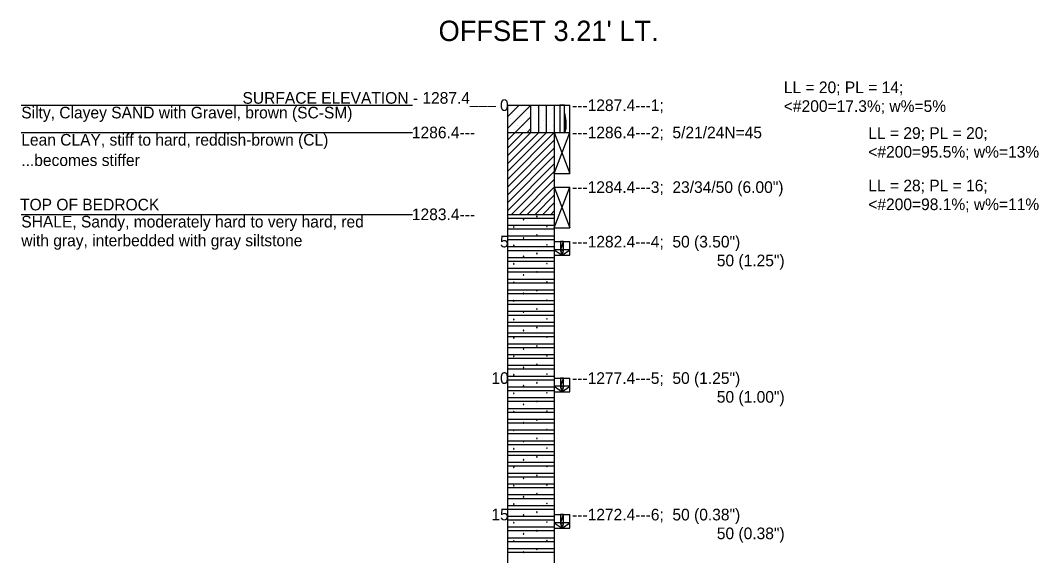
# Model space of a CAD drawing. Extents: x -6 to 173, y 24 to 64.
# Drawn here: x 54.9 to 65.75, y 44.93 to 50.63 of the extents above; entities that cross this region are included whole.
import ezdxf

# ---------------------------------------------------------------- set-up
doc = ezdxf.new("R2010")
doc.units = 0

# ---------------------------------------------------------------- blocks, each defined once
blk = doc.blocks.new('POINT_DISPLAY')
blk.add_line((0, 0), (0, 0))

msp = doc.modelspace()

# ---------------------------------------------------------------- linework, layer by layer
for points in [[(54.91, 49.727), (59.077, 49.727)], [(60.089, 49.602), (60.214, 49.727)], [(60.089, 49.477), (60.339, 49.727)], [(60.089, 49.727), (60.089, 39.553)], [(60.089, 49.727), (60.589, 49.727)], [(60.339, 49.436), (60.339, 49.727)], [(60.423, 49.436), (60.423, 49.727)], [(60.506, 49.436), (60.506, 49.727)], [(60.589, 49.727), (60.756, 49.727)], [(60.589, 49.727), (60.589, 39.553)], [(60.756, 49.436), (60.756, 49.727)], [(60.174, 49.436), (60.339, 49.602)], [(60.299, 49.436), (60.339, 49.477)], [(54.91, 49.436), (59.077, 49.436)], [(60.089, 49.436), (60.589, 49.436)], [(60.089, 49.353), (60.173, 49.436)], [(60.089, 49.27), (60.256, 49.436)], [(60.089, 49.186), (60.339, 49.436)], [(60.089, 49.103), (60.423, 49.436)], [(60.089, 49.02), (60.506, 49.436)], [(60.089, 48.936), (60.589, 49.436)], [(60.589, 49.436), (60.756, 49.436)], [(60.589, 49.436), (60.756, 49)], [(60.589, 49), (60.756, 49.436)], [(60.589, 49.436), (60.756, 49.436)], [(60.756, 49), (60.756, 49.436)], [(60.089, 48.853), (60.589, 49.353)], [(60.089, 48.77), (60.589, 49.27)], [(60.089, 48.686), (60.589, 49.186)], [(60.089, 48.603), (60.589, 49.103)], [(60.134, 48.564), (60.589, 49.02)], [(60.217, 48.564), (60.589, 48.936)], [(60.589, 49), (60.756, 49)], [(60.301, 48.564), (60.589, 48.853)], [(60.589, 48.855), (60.756, 48.419)], [(60.589, 48.419), (60.756, 48.855)], [(60.589, 48.855), (60.756, 48.855)], [(60.756, 48.419), (60.756, 48.855)], [(60.384, 48.564), (60.589, 48.77)], [(60.467, 48.564), (60.589, 48.686)], [(54.91, 48.564), (59.077, 48.564)], [(60.089, 48.564), (60.589, 48.564)], [(60.089, 48.564), (60.589, 48.564)], [(60.089, 48.525), (60.589, 48.525)], [(60.264, 48.508), (60.263, 48.511), (60.26, 48.511), (60.258, 48.509), (60.26, 48.506), (60.263, 48.506), (60.264, 48.508)], [(60.407, 48.54), (60.405, 48.543), (60.402, 48.543), (60.4, 48.54), (60.402, 48.538), (60.405, 48.538), (60.407, 48.54)], [(60.551, 48.564), (60.589, 48.603)], [(60.089, 48.449), (60.589, 48.449)], [(60.089, 48.41), (60.589, 48.41)], [(60.16, 48.43), (60.158, 48.432), (60.155, 48.432), (60.153, 48.43), (60.155, 48.427), (60.158, 48.427), (60.16, 48.43)], [(60.513, 48.436), (60.511, 48.439), (60.508, 48.439), (60.506, 48.436), (60.508, 48.433), (60.511, 48.433), (60.513, 48.436)], [(60.589, 48.419), (60.756, 48.419)], [(60.089, 48.335), (60.589, 48.335)], [(60.089, 48.295), (60.589, 48.295)], [(60.264, 48.312), (60.263, 48.314), (60.26, 48.314), (60.258, 48.312), (60.26, 48.309), (60.263, 48.309), (60.264, 48.312)], [(60.407, 48.343), (60.405, 48.346), (60.402, 48.346), (60.4, 48.343), (60.402, 48.341), (60.405, 48.341), (60.407, 48.343)], [(60.089, 48.22), (60.589, 48.22)], [(60.089, 48.18), (60.589, 48.18)], [(60.16, 48.233), (60.158, 48.235), (60.155, 48.235), (60.153, 48.233), (60.155, 48.23), (60.158, 48.23), (60.16, 48.233)], [(60.513, 48.239), (60.511, 48.242), (60.508, 48.242), (60.506, 48.239), (60.508, 48.236), (60.511, 48.236), (60.513, 48.239)], [(60.589, 48.274), (60.756, 48.274)], [(60.756, 48.128), (60.756, 48.274)], [(60.089, 48.105), (60.589, 48.105)], [(60.089, 48.066), (60.589, 48.066)], [(60.264, 48.115), (60.263, 48.118), (60.26, 48.118), (60.258, 48.115), (60.26, 48.112), (60.263, 48.112), (60.264, 48.115)], [(60.407, 48.147), (60.405, 48.149), (60.402, 48.149), (60.4, 48.147), (60.402, 48.144), (60.405, 48.144), (60.407, 48.147)], [(60.589, 48.128), (60.756, 48.128)], [(60.089, 47.99), (60.589, 47.99)], [(60.16, 48.036), (60.158, 48.039), (60.155, 48.039), (60.153, 48.036), (60.155, 48.033), (60.158, 48.033), (60.16, 48.036)], [(60.513, 48.042), (60.511, 48.045), (60.508, 48.045), (60.506, 48.042), (60.508, 48.039), (60.511, 48.039), (60.513, 48.042)], [(60.089, 47.951), (60.589, 47.951)], [(60.089, 47.875), (60.589, 47.875)], [(60.264, 47.918), (60.263, 47.921), (60.26, 47.921), (60.258, 47.918), (60.26, 47.915), (60.263, 47.915), (60.264, 47.918)], [(60.407, 47.95), (60.405, 47.953), (60.402, 47.953), (60.4, 47.95), (60.402, 47.947), (60.405, 47.947), (60.407, 47.95)], [(60.513, 47.845), (60.511, 47.848), (60.508, 47.848), (60.506, 47.845), (60.508, 47.843), (60.511, 47.843), (60.513, 47.845)], [(60.089, 47.836), (60.589, 47.836)], [(60.089, 47.76), (60.589, 47.76)], [(60.16, 47.839), (60.158, 47.842), (60.155, 47.842), (60.153, 47.839), (60.155, 47.836), (60.158, 47.836), (60.16, 47.839)], [(60.407, 47.753), (60.405, 47.756), (60.402, 47.756), (60.4, 47.753), (60.402, 47.75), (60.405, 47.75), (60.407, 47.753)], [(60.089, 47.721), (60.589, 47.721)], [(60.089, 47.646), (60.589, 47.646)], [(60.16, 47.642), (60.158, 47.645), (60.155, 47.645), (60.153, 47.642), (60.155, 47.639), (60.158, 47.639), (60.16, 47.642)], [(60.264, 47.721), (60.263, 47.724), (60.26, 47.724), (60.258, 47.721), (60.26, 47.718), (60.263, 47.718), (60.264, 47.721)], [(60.513, 47.649), (60.511, 47.651), (60.508, 47.651), (60.506, 47.649), (60.508, 47.646), (60.511, 47.646), (60.513, 47.649)], [(60.089, 47.606), (60.589, 47.606)], [(60.089, 47.531), (60.589, 47.531)], [(60.264, 47.524), (60.263, 47.527), (60.26, 47.527), (60.258, 47.524), (60.26, 47.521), (60.263, 47.521), (60.264, 47.524)], [(60.407, 47.556), (60.405, 47.559), (60.402, 47.559), (60.4, 47.556), (60.402, 47.553), (60.405, 47.553), (60.407, 47.556)], [(60.089, 47.491), (60.589, 47.491)], [(60.089, 47.416), (60.589, 47.416)], [(60.16, 47.445), (60.158, 47.448), (60.155, 47.448), (60.153, 47.445), (60.155, 47.442), (60.158, 47.442), (60.16, 47.445)], [(60.513, 47.452), (60.511, 47.455), (60.508, 47.455), (60.506, 47.452), (60.508, 47.449), (60.511, 47.449), (60.513, 47.452)], [(60.089, 47.377), (60.589, 47.377)], [(60.264, 47.327), (60.263, 47.33), (60.26, 47.33), (60.258, 47.327), (60.26, 47.325), (60.263, 47.325), (60.264, 47.327)], [(60.407, 47.359), (60.405, 47.362), (60.402, 47.362), (60.4, 47.359), (60.402, 47.356), (60.405, 47.356), (60.407, 47.359)], [(60.089, 47.301), (60.589, 47.301)], [(60.089, 47.262), (60.589, 47.262)], [(60.16, 47.248), (60.158, 47.251), (60.155, 47.251), (60.153, 47.248), (60.155, 47.246), (60.158, 47.246), (60.16, 47.248)], [(60.513, 47.255), (60.511, 47.258), (60.508, 47.258), (60.506, 47.255), (60.508, 47.252), (60.511, 47.252), (60.513, 47.255)], [(60.089, 47.186), (60.589, 47.186)], [(60.089, 47.147), (60.589, 47.147)], [(60.264, 47.13), (60.263, 47.133), (60.26, 47.133), (60.258, 47.131), (60.26, 47.128), (60.263, 47.128), (60.264, 47.13)], [(60.407, 47.162), (60.405, 47.165), (60.402, 47.165), (60.4, 47.162), (60.402, 47.16), (60.405, 47.16), (60.407, 47.162)], [(60.089, 47.072), (60.589, 47.072)], [(60.089, 47.032), (60.589, 47.032)], [(60.16, 47.052), (60.158, 47.054), (60.155, 47.054), (60.153, 47.052), (60.155, 47.049), (60.158, 47.049), (60.16, 47.052)], [(60.513, 47.058), (60.511, 47.061), (60.508, 47.061), (60.506, 47.058), (60.508, 47.055), (60.511, 47.055), (60.513, 47.058)], [(60.089, 46.957), (60.589, 46.957)], [(60.089, 46.917), (60.589, 46.917)], [(60.264, 46.934), (60.263, 46.937), (60.26, 46.937), (60.258, 46.934), (60.26, 46.931), (60.263, 46.931), (60.264, 46.934)], [(60.407, 46.966), (60.405, 46.968), (60.402, 46.968), (60.4, 46.966), (60.402, 46.963), (60.405, 46.963), (60.407, 46.966)], [(60.089, 46.842), (60.589, 46.842)], [(60.089, 46.802), (60.589, 46.802)], [(60.16, 46.855), (60.158, 46.858), (60.155, 46.858), (60.153, 46.855), (60.155, 46.852), (60.158, 46.852), (60.16, 46.855)], [(60.407, 46.769), (60.405, 46.772), (60.402, 46.772), (60.4, 46.769), (60.402, 46.766), (60.405, 46.766), (60.407, 46.769)], [(60.513, 46.861), (60.511, 46.864), (60.508, 46.864), (60.506, 46.861), (60.508, 46.858), (60.511, 46.858), (60.513, 46.861)], [(60.589, 46.82), (60.756, 46.82)], [(60.756, 46.675), (60.756, 46.82)], [(60.089, 46.727), (60.589, 46.727)], [(60.089, 46.688), (60.589, 46.688)], [(60.16, 46.658), (60.158, 46.661), (60.155, 46.661), (60.153, 46.658), (60.155, 46.655), (60.158, 46.655), (60.16, 46.658)], [(60.264, 46.737), (60.263, 46.74), (60.26, 46.74), (60.258, 46.737), (60.26, 46.734), (60.263, 46.734), (60.264, 46.737)], [(60.513, 46.664), (60.511, 46.667), (60.508, 46.667), (60.506, 46.664), (60.508, 46.662), (60.511, 46.662), (60.513, 46.664)], [(60.589, 46.675), (60.756, 46.675)], [(60.089, 46.612), (60.589, 46.612)], [(60.089, 46.573), (60.589, 46.573)], [(60.407, 46.572), (60.405, 46.575), (60.402, 46.575), (60.4, 46.572), (60.402, 46.569), (60.405, 46.569), (60.407, 46.572)], [(60.089, 46.497), (60.589, 46.497)], [(60.089, 46.458), (60.589, 46.458)], [(60.16, 46.461), (60.158, 46.464), (60.155, 46.464), (60.153, 46.461), (60.155, 46.458), (60.158, 46.458), (60.16, 46.461)], [(60.264, 46.54), (60.263, 46.543), (60.26, 46.543), (60.258, 46.54), (60.26, 46.537), (60.263, 46.537), (60.264, 46.54)], [(60.513, 46.468), (60.511, 46.47), (60.508, 46.47), (60.506, 46.468), (60.508, 46.465), (60.511, 46.465), (60.513, 46.468)], [(60.089, 46.383), (60.589, 46.383)], [(60.089, 46.343), (60.589, 46.343)], [(60.264, 46.343), (60.263, 46.346), (60.26, 46.346), (60.258, 46.343), (60.26, 46.34), (60.263, 46.34), (60.264, 46.343)], [(60.407, 46.375), (60.405, 46.378), (60.402, 46.378), (60.4, 46.375), (60.402, 46.372), (60.405, 46.372), (60.407, 46.375)], [(60.089, 46.268), (60.589, 46.268)], [(60.089, 46.228), (60.589, 46.228)], [(60.16, 46.264), (60.158, 46.267), (60.155, 46.267), (60.153, 46.264), (60.155, 46.261), (60.158, 46.261), (60.16, 46.264)], [(60.513, 46.271), (60.511, 46.274), (60.508, 46.274), (60.506, 46.271), (60.508, 46.268), (60.511, 46.268), (60.513, 46.271)], [(60.089, 46.153), (60.589, 46.153)], [(60.089, 46.114), (60.589, 46.114)], [(60.264, 46.146), (60.263, 46.149), (60.26, 46.149), (60.258, 46.146), (60.26, 46.143), (60.263, 46.143), (60.264, 46.146)], [(60.407, 46.178), (60.405, 46.181), (60.402, 46.181), (60.4, 46.178), (60.402, 46.175), (60.405, 46.175), (60.407, 46.178)], [(60.089, 46.038), (60.589, 46.038)], [(60.16, 46.067), (60.158, 46.07), (60.155, 46.07), (60.153, 46.067), (60.155, 46.064), (60.158, 46.064), (60.16, 46.067)], [(60.513, 46.074), (60.511, 46.077), (60.508, 46.077), (60.506, 46.074), (60.508, 46.071), (60.511, 46.071), (60.513, 46.074)], [(60.089, 45.999), (60.589, 45.999)], [(60.089, 45.923), (60.589, 45.923)], [(60.264, 45.949), (60.263, 45.952), (60.26, 45.952), (60.258, 45.949), (60.26, 45.947), (60.263, 45.947), (60.264, 45.949)], [(60.407, 45.981), (60.405, 45.984), (60.402, 45.984), (60.4, 45.981), (60.402, 45.978), (60.405, 45.978), (60.407, 45.981)], [(60.089, 45.884), (60.589, 45.884)], [(60.089, 45.808), (60.589, 45.808)], [(60.16, 45.87), (60.158, 45.873), (60.155, 45.873), (60.153, 45.87), (60.155, 45.868), (60.158, 45.868), (60.16, 45.87)], [(60.407, 45.784), (60.405, 45.787), (60.402, 45.787), (60.4, 45.784), (60.402, 45.782), (60.405, 45.782), (60.407, 45.784)], [(60.513, 45.877), (60.511, 45.88), (60.508, 45.88), (60.506, 45.877), (60.508, 45.874), (60.511, 45.874), (60.513, 45.877)], [(60.089, 45.769), (60.589, 45.769)], [(60.089, 45.694), (60.589, 45.694)], [(60.264, 45.753), (60.263, 45.755), (60.26, 45.755), (60.258, 45.753), (60.26, 45.75), (60.263, 45.75), (60.264, 45.753)], [(60.513, 45.68), (60.511, 45.683), (60.508, 45.683), (60.506, 45.68), (60.508, 45.677), (60.511, 45.677), (60.513, 45.68)], [(60.089, 45.654), (60.589, 45.654)], [(60.089, 45.579), (60.589, 45.579)], [(60.16, 45.674), (60.158, 45.676), (60.155, 45.676), (60.153, 45.674), (60.155, 45.671), (60.158, 45.671), (60.16, 45.674)], [(60.407, 45.588), (60.405, 45.59), (60.402, 45.59), (60.4, 45.588), (60.402, 45.585), (60.405, 45.585), (60.407, 45.588)], [(60.089, 45.539), (60.589, 45.539)], [(60.089, 45.464), (60.589, 45.464)], [(60.16, 45.477), (60.158, 45.48), (60.155, 45.48), (60.153, 45.477), (60.155, 45.474), (60.158, 45.474), (60.16, 45.477)], [(60.264, 45.556), (60.263, 45.559), (60.26, 45.559), (60.258, 45.556), (60.26, 45.553), (60.263, 45.553), (60.264, 45.556)], [(60.513, 45.483), (60.511, 45.486), (60.508, 45.486), (60.506, 45.483), (60.508, 45.48), (60.511, 45.48), (60.513, 45.483)], [(60.089, 45.425), (60.589, 45.425)], [(60.264, 45.359), (60.263, 45.362), (60.26, 45.362), (60.258, 45.359), (60.26, 45.356), (60.263, 45.356), (60.264, 45.359)], [(60.407, 45.391), (60.405, 45.394), (60.402, 45.394), (60.4, 45.391), (60.402, 45.388), (60.405, 45.388), (60.407, 45.391)], [(60.589, 45.367), (60.756, 45.367)], [(60.756, 45.221), (60.756, 45.367)], [(60.089, 45.349), (60.589, 45.349)], [(60.089, 45.31), (60.589, 45.31)], [(60.16, 45.28), (60.158, 45.283), (60.155, 45.283), (60.153, 45.28), (60.155, 45.277), (60.158, 45.277), (60.16, 45.28)], [(60.513, 45.286), (60.511, 45.289), (60.508, 45.289), (60.506, 45.286), (60.508, 45.284), (60.511, 45.284), (60.513, 45.286)], [(60.089, 45.234), (60.589, 45.234)], [(60.089, 45.195), (60.589, 45.195)], [(60.264, 45.162), (60.263, 45.165), (60.26, 45.165), (60.258, 45.162), (60.26, 45.159), (60.263, 45.159), (60.264, 45.162)], [(60.407, 45.194), (60.405, 45.197), (60.402, 45.197), (60.4, 45.194), (60.402, 45.191), (60.405, 45.191), (60.407, 45.194)], [(60.589, 45.221), (60.756, 45.221)], [(60.089, 45.119), (60.589, 45.119)], [(60.089, 45.08), (60.589, 45.08)], [(60.16, 45.083), (60.158, 45.086), (60.155, 45.086), (60.153, 45.083), (60.155, 45.08), (60.158, 45.08), (60.16, 45.083)], [(60.513, 45.09), (60.511, 45.092), (60.508, 45.092), (60.506, 45.09), (60.508, 45.087), (60.511, 45.087), (60.513, 45.09)], [(60.089, 45.005), (60.589, 45.005)], [(60.089, 44.965), (60.589, 44.965)], [(60.264, 44.965), (60.263, 44.968), (60.26, 44.968), (60.258, 44.965), (60.26, 44.962), (60.263, 44.962), (60.264, 44.965)], [(60.407, 44.997), (60.405, 45), (60.402, 45), (60.4, 44.997), (60.402, 44.994), (60.405, 44.994), (60.407, 44.997)]]:
    msp.add_lwpolyline(points)
for points in [[(60.648, 49.727), (60.648, 49.436), (60.698, 49.436), (60.698, 49.727)], [(60.712, 49.56), (60.706, 49.602), (60.698, 49.642), (60.712, 49.56)], [(60.698, 49.642), (60.698, 49.436), (60.712, 49.56), (60.698, 49.642)], [(60.698, 49.436), (60.712, 49.477), (60.712, 49.56), (60.698, 49.436)], [(60.698, 49.436), (60.706, 49.436), (60.712, 49.477), (60.698, 49.436)], [(60.712, 49.477), (60.714, 49.519), (60.712, 49.56), (60.712, 49.477)], [(60.656, 48.186), (60.589, 48.186), (60.673, 48.128), (60.656, 48.186)], [(60.656, 48.186), (60.689, 48.186), (60.689, 48.274), (60.656, 48.186)], [(60.656, 48.186), (60.689, 48.274), (60.656, 48.274), (60.656, 48.186)], [(60.656, 48.186), (60.673, 48.128), (60.689, 48.186), (60.656, 48.186)], [(60.673, 48.128), (60.756, 48.186), (60.689, 48.186), (60.673, 48.128)], [(60.656, 46.733), (60.689, 46.733), (60.689, 46.82), (60.656, 46.733)], [(60.656, 46.733), (60.689, 46.82), (60.656, 46.82), (60.656, 46.733)], [(60.656, 46.733), (60.589, 46.733), (60.673, 46.675), (60.656, 46.733)], [(60.656, 46.733), (60.673, 46.675), (60.689, 46.733), (60.656, 46.733)], [(60.673, 46.675), (60.756, 46.733), (60.689, 46.733), (60.673, 46.675)], [(60.656, 45.279), (60.689, 45.279), (60.689, 45.367), (60.656, 45.279)], [(60.656, 45.279), (60.689, 45.367), (60.656, 45.367), (60.656, 45.279)], [(60.656, 45.279), (60.589, 45.279), (60.673, 45.221), (60.656, 45.279)], [(60.656, 45.279), (60.673, 45.221), (60.689, 45.279), (60.656, 45.279)], [(60.673, 45.221), (60.756, 45.279), (60.689, 45.279), (60.673, 45.221)]]:
    msp.add_lwpolyline(points, close=True)

# ---------------------------------------------------------------- block references
at = {"xscale": 0.01, "yscale": 0.01}
for p in [(60.119, 49.715), (60.244, 49.715), (60.408, 49.702), (60.494, 49.715), (60.094, 49.665), (60.119, 49.59), (60.144, 49.64), (60.169, 49.69), (60.194, 49.615), (60.261, 49.667), (60.294, 49.64), (60.319, 49.69), (60.369, 49.64), (60.419, 49.59), (60.444, 49.665), (60.494, 49.615), (60.544, 49.64), (60.569, 49.69), (60.094, 49.49), (60.144, 49.54), (60.194, 49.515), (60.244, 49.565), (60.258, 49.507), (60.306, 49.583), (60.319, 49.54), (60.407, 49.526), (60.444, 49.49), (60.475, 49.561), (60.494, 49.515), (60.536, 49.558), (60.569, 49.515), (60.585, 49.565), (60.169, 49.465), (60.219, 49.44), (60.296, 49.454), (60.344, 49.465), (60.394, 49.44), (60.544, 49.465)]:
    msp.add_blockref('POINT_DISPLAY', p, dxfattribs=at)

# ---------------------------------------------------------------- texts
for s, height, p in [("OFFSET 3.21' LT.", 0.217, (59.356, 50.41)), ('LL = 20; PL = 14;', 0.124, (63.035, 49.855)), ('SURFACE ELEVATION - 1287.4___', 0.124, (57.267, 49.742)), ('Silty, Clayey SAND with Gravel, brown (SC-SM)', 0.124, (54.91, 49.586)), ('0', 0.124, (60.011, 49.665)), ('---1287.4---1;', 0.124, (60.779, 49.664)), ('<#200=17.3%; w%=5%', 0.124, (63.035, 49.655)), ('1286.4---', 0.124, (59.072, 49.374)), ('---1286.4---2;  5/21/24N=45', 0.124, (60.779, 49.374)), ('LL = 29; PL = 20;', 0.124, (63.935, 49.368)), ('Lean CLAY, stiff to hard, reddish-brown (CL)', 0.124, (54.91, 49.296)), ('<#200=95.5%; w%=13%', 0.124, (63.935, 49.168)), ('...becomes stiffer', 0.124, (54.91, 49.079)), ('LL = 28; PL = 16;', 0.124, (63.935, 48.809)), ('---1284.4---3;  23/34/50 (6.00")', 0.124, (60.779, 48.792)), ('TOP OF BEDROCK', 0.124, (54.897, 48.606)), ('<#200=98.1%; w%=11%', 0.124, (63.935, 48.609)), ('1283.4---', 0.124, (59.072, 48.502)), ('SHALE, Sandy, moderately hard to very hard, red', 0.124, (54.91, 48.424)), ('with gray, interbedded with gray siltstone', 0.124, (54.91, 48.224)), ('5', 0.124, (60.011, 48.212)), ('---1282.4---4;  50 (3.50")', 0.124, (60.779, 48.211)), ('50 (1.25")', 0.124, (62.321, 48.011)), ('10', 0.124, (59.919, 46.758)), ('---1277.4---5;  50 (1.25")', 0.124, (60.779, 46.758)), ('50 (1.00")', 0.124, (62.321, 46.558)), ('15', 0.124, (59.919, 45.305)), ('---1272.4---6;  50 (0.38")', 0.124, (60.779, 45.304)), ('50 (0.38")', 0.124, (62.321, 45.104))]:
    msp.add_text(s, height=height).set_placement(p)

doc.saveas('drawing.dxf')
